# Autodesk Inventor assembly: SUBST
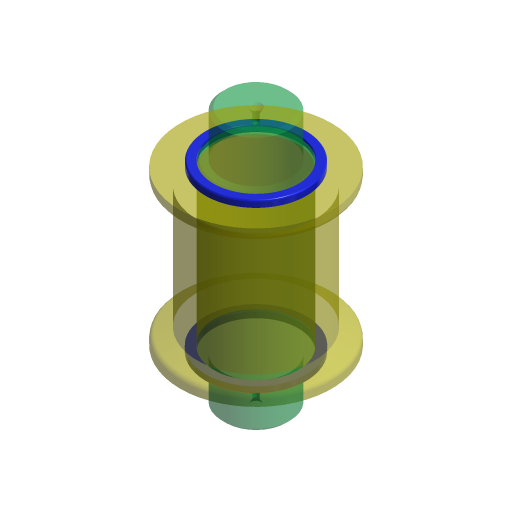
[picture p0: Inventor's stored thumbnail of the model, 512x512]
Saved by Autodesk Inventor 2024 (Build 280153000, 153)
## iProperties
Created: 2023-03
Part Number: SUBST
Document SubType Name: Assembly
Designer: Andrzej Jaskulski
Checked By: A.J.
Engr Approved By: Andrzej Jaskulski
Mfg Approved By: Andrzej Jaskulski
Authority: A.J.
Company: ATC
Control State: 0
Master: False
Checked Out: False
Shininess: 20.0
Length Units: 11269
Angle Units: 11279
Time Units: 11290
Mass Units: 11283
Length Display Precision: 3
Angle Display Precision: 2
Compacted: True
Density: 0.0
Volumn: 0.0
Area: 0.0
PropertySet Name: Model Information
Title: A.J.: Kurs R2024-MEP
Author: Andrzej Jaskulski
Revision Number: 1/24
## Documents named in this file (4)
- C:\Users\AndJas\Documents\R2024-MEP\Obszar roboczy\SUBST.iam
- C:\Users\AndJas\Documents\R2024-MEP\Obszar roboczy\Wałek.ipt
- C:\Users\AndJas\Documents\R2024-MEP\Obszar roboczy\Podkładka.ipt
- C:\Users\AndJas\Documents\R2024-MEP\Obszar roboczy\Rolka.ipt
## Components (4 placed, 3 different names)
1. Wałek:1 — Wstawiające:3
2. Podkładka:1 — Wstawiające:2, Wstawiające:3
3. Podkładka:2 — Wstawiające:1
4. Rolka:1 — Wstawiające:1, Wstawiające:2
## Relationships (3: Insert 3)
- Wstawiające:1 [Insert]: Podkładka:2 ↔ Rolka:1
- Wstawiające:2 [Insert]: Podkładka:1 ↔ Rolka:1
- Wstawiające:3 [Insert]: Wałek:1 ↔ Podkładka:1
